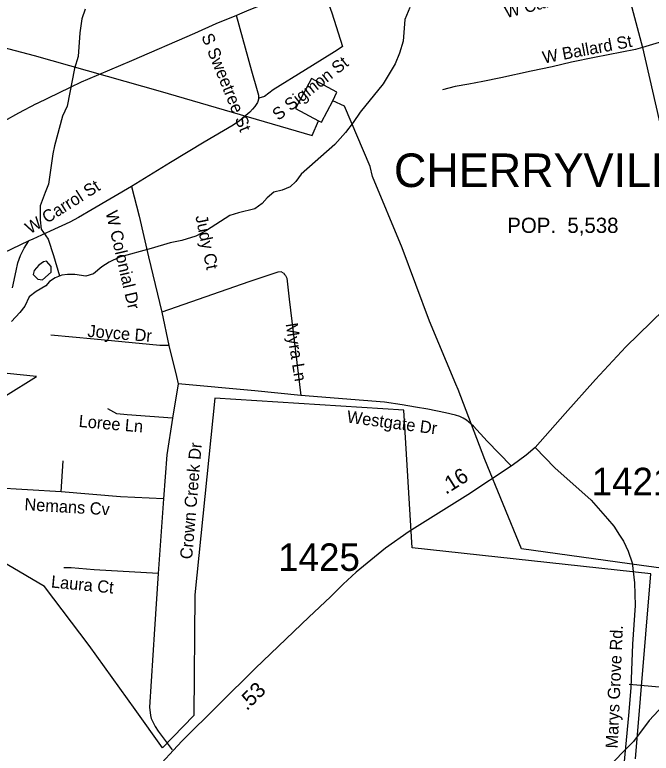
# Model space of a CAD drawing. Extents: x 1268485 to 1426702, y 514839 to 616766.
# Drawn here: x 1285826 to 1289245, y 595436 to 599406 of the extents above; entities that cross this region are included whole.
import ezdxf

# ---------------------------------------------------------------- set-up
doc = ezdxf.new("R2010")
doc.units = 0
for name, color, linetype in [('Old_Level_10', 7, 'Continuous'), ('Old_Level_11', 7, 'Continuous'), ('Old_Level_17', 7, 'Continuous'), ('Old_Level_32', 7, 'Continuous'), ('Old_Level_35', 7, 'Continuous'), ('Old_Level_48', 7, 'Continuous'), ('Old_Level_49', 7, 'Continuous'), ('Old_Level_56', 7, 'Continuous'), ('Old_Level_62', 7, 'Continuous'), ('Old_Level_8', 7, 'Continuous'), ('Old_Level_9', 7, 'Continuous')]:
    doc.layers.add(name, color=color, linetype=linetype)

msp = doc.modelspace()

# ---------------------------------------------------------------- linework, layer by layer
at = {"layer": 'Old_Level_32'}
for points in [[(1291373.236, 599052.963), (1291042.485, 598962.222), (1290896.068, 598918.096), (1290714.369, 598868.675), (1290626.166, 598839.552), (1290393.37, 598736.035), (1290251.442, 598663.453), (1290079.286, 598556.102), (1290045.769, 598531.391), (1289973.441, 598467.85), (1289871.596, 598364.18), (1289673.146, 598175.239), (1289517.331, 598019.095), (1289109.386, 597620.624), (1288945.325, 597445.883), (1288783.028, 597262.317), (1288622.05, 597079.622)], [(1288622.05, 597079.622), (1288572.393, 597038.158), (1288497.215, 596983.49), (1288260.148, 596824.586), (1287944.218, 596628.834), (1287817.925, 596537.729), (1287660.673, 596409.627), (1287589.144, 596345.233), (1287521.339, 596276.962), (1287404.685, 596167.653), (1287119.817, 595892.644), (1286723.931, 595500.009), (1286678.393, 595451.758), (1286614.957, 595384.542), (1286400.649, 595135.726), (1286252.429, 594959.218), (1286198.695, 594877.861), (1286130.586, 594756.275), (1286065.2, 594633.367), (1286021.61, 594555.394)], [(1288622.05, 597079.622), (1288726.94, 596969.93), (1288923.097, 596796.803), (1289010.597, 596695.735), (1289044.114, 596656.904), (1289074.104, 596609.248), (1289096.096, 596576.098), (1289121.978, 596523.235), (1289142.904, 596459.219), (1289154.67, 596351.428), (1289158.757, 596231.164), (1289145.135, 596022.353), (1289135.047, 595786.899), (1289122.674, 595639.228), (1289095.159, 595335.828), (1289082.775, 595157.988)]]:
    msp.add_lwpolyline(points, dxfattribs=at)
at = {"layer": 'Old_Level_35'}
for p, q in [((1289089.245, 599646.829), (1289197.512, 599230.009)), ((1289197.512, 599230.009), (1289304.755, 598761.055)), ((1286615.907, 597806.743), (1286654.149, 597627.681)), ((1286703.361, 597422.936), (1286672.603, 597238.236)), ((1286074.877, 596840.691), (1286085.949, 597008.988)), ((1286624.826, 596803.628), (1286595.606, 596402.392))]:
    msp.add_line(p, q, dxfattribs=at)
for points in [[(1287467.898, 599584.442), (1287422.274, 599565.167), (1287082.298, 599431.626), (1287032.88, 599410.353), (1287016.271, 599402.458)], [(1287467.898, 599584.442), (1287529.619, 599415.94), (1287587.238, 599235.699)], [(1287016.271, 599402.458), (1286905.338, 599357.705), (1286790.508, 599305.417), (1286451.967, 599159.574), (1286215.953, 599058.329), (1286182.119, 599043.463), (1286123.987, 599014.705), (1285942.516, 598927.916)], [(1287136.124, 598957.956), (1287136.636, 598971.746), (1287130.075, 598996.865), (1287099.727, 599103.236), (1287016.271, 599402.458)], [(1289594.083, 599362.114), (1289521.392, 599333.151), (1289376.42, 599284.707), (1289197.512, 599230.009)], [(1287587.238, 599235.699), (1287557.301, 599216.424), (1287529.721, 599198.79), (1287386.902, 599110.105), (1287214.351, 599003.324), (1287166.471, 598966.415), (1287136.124, 598957.956)], [(1289197.512, 599230.009), (1289161.218, 599220.269), (1288940.172, 599177.208), (1288817.038, 599151.269), (1288712.052, 599126.919), (1288600.298, 599102.98), (1288436.872, 599068.172), (1288339.985, 599047.513), (1288265.14, 599034.133), (1288192.45, 599020.394), (1288123.655, 599002.914)], [(1287136.124, 598957.956), (1287129.665, 598934.068), (1287115.106, 598912.435), (1287102.905, 598898.388), (1287089.372, 598883.164), (1287056.153, 598855.02), (1287032.367, 598835.899), (1286999.149, 598812.164), (1286844.027, 598721.685), (1286662.146, 598611.521), (1286452.583, 598483.876)], [(1285942.516, 598927.916), (1285941.388, 598927.353), (1285845.423, 598877.576), (1285769.349, 598833.541), (1285716.548, 598804.834), (1285656.263, 598774.179), (1285614.125, 598756.134), (1285562.657, 598736.602), (1285562.041, 598736.5)], [(1286452.583, 598483.876), (1286241.994, 598359.614), (1286167.355, 598316.195), (1286121.218, 598290.871), (1286015.001, 598242.94), (1285923.241, 598200.801), (1285901.095, 598190.856), (1285716.651, 598104.017)], [(1286452.583, 598483.876), (1286494.721, 598324.14), (1286544.856, 598104.889), (1286615.907, 597806.743)], [(1285814.255, 597938.899), (1285832.403, 598030.3), (1285842.758, 598071.926), (1285856.701, 598111.245), (1285875.771, 598151.076), (1285901.095, 598190.856)], [(1287270.125, 598017.075), (1287256.797, 598024.251), (1287239.265, 598021.996), (1287223.168, 598017.485), (1287083.528, 597970.99), (1286615.907, 597806.743)], [(1287270.125, 598017.075), (1287275.149, 598010.77), (1287280.48, 598003.951), (1287286.529, 597989.444), (1287299.96, 597877.229), (1287363.219, 597358.96)], [(1286654.149, 597627.681), (1286604.424, 597627.681), (1286252.042, 597662.437), (1286018.59, 597684.122)], [(1286654.149, 597627.681), (1286695.262, 597461.435), (1286703.361, 597422.936)], [(1287363.219, 597358.96), (1287115.516, 597384.541), (1286703.361, 597422.936)], [(1288492.646, 596981.101), (1288363.873, 597114.538), (1288289.952, 597194.15), (1288253.042, 597226.445), (1288235.1, 597238.236), (1288216.133, 597246.951), (1288193.987, 597253.102), (1288139.649, 597266.431), (1288044.299, 597285.449), (1287978.99, 597297.239), (1287906.094, 597310.055), (1287811.77, 597322.871), (1287699.402, 597332.611), (1287363.219, 597358.96)], [(1286672.603, 597238.236), (1286429.104, 597254.691), (1286373.535, 597260.997), (1286325.655, 597287.704)], [(1286672.603, 597238.236), (1286642.358, 597039.643), (1286624.826, 596803.628)], [(1286074.877, 596840.691), (1285711.524, 596863.298), (1285656.673, 596875.704)], [(1286624.826, 596803.628), (1286393.733, 596815.367), (1286074.877, 596840.691)], [(1286595.606, 596402.392), (1286251.837, 596422.692), (1286128.395, 596432.637), (1286088.615, 596433.509)], [(1286595.606, 596402.392), (1286575.614, 596103.683), (1286549.982, 595682.916), (1286554.083, 595638.317), (1286559.21, 595622.938), (1286579.715, 595579.826), (1286596.119, 595554.143), (1286671.578, 595454.641)], [(1289127.282, 595806.818), (1289369.346, 595786.518), (1289417.841, 595783.391), (1289457.108, 595781.649), (1289515.548, 595792.311), (1289613.05, 595811.894), (1289715.371, 595834.142), (1289774.631, 595843.933), (1289832.866, 595855.057), (1289888.128, 595866.643), (1289925.96, 595872.025), (1289962.049, 595873.307), (1289999.881, 595870.179), (1290033.202, 595862.644), (1290067.958, 595847.521), (1290100.972, 595826.145), (1290134.908, 595797.181), (1290170.484, 595754.427), (1290236.409, 595647.134), (1290262.963, 595601.766)]]:
    msp.add_lwpolyline(points, dxfattribs=at)
at = {"layer": 'Old_Level_48'}
for points in [[(1285440.364, 597149.866), (1285941.557, 597461.072), (1285239.886, 597532.39)], [(1289160.786, 595405.264), (1289243.583, 596401.2), (1287961.566, 596540.764), (1287915.791, 597281.367), (1286900.507, 597344.37), (1286793.585, 596287.566), (1286786.902, 595639.221), (1286619.838, 595464.167), (1286472.821, 595671.638), (1286225.566, 596015.261), (1285984.993, 596332.951), (1285189.767, 596799.759)]]:
    msp.add_lwpolyline(points, dxfattribs=at)
at = {"layer": 'Old_Level_49'}
for points in [[(1285440.364, 597149.866), (1285941.557, 597461.072), (1285239.886, 597532.39)], [(1289160.786, 595405.264), (1289243.583, 596401.2), (1287961.566, 596540.764), (1287915.791, 597281.367), (1286900.507, 597344.37), (1286793.585, 596287.566), (1286786.902, 595639.221), (1286619.838, 595464.167), (1286472.821, 595671.638), (1286225.566, 596015.261), (1285984.993, 596332.951), (1285189.767, 596799.759)]]:
    msp.add_lwpolyline(points, dxfattribs=at)
at = {"layer": 'Old_Level_56'}
for points in [[(1281527.068, 597048.671), (1281959.235, 597378.004), (1281983.877, 597409.325), (1282381.702, 597629.835), (1282734.399, 597815.234), (1282772.921, 597840.272), (1283101.299, 598010.353), (1283429.918, 598192.435), (1283882.463, 598447.462), (1284371.248, 598713.564), (1284930.959, 599014.058), (1285446.39, 599301.636), (1285512.31, 599296.107), (1285929.727, 599187.655), (1286607.573, 598994.921), (1287424.172, 598756.774), (1287458.18, 598835.93)], [(1287534.796, 598944.244), (1287555.919, 598989.642), (1287419.534, 599063.222), (1287333.672, 598903.069), (1287458.18, 598835.93)], [(1287458.18, 598835.93), (1287473.861, 598829.611), (1287534.796, 598944.244)], [(1290886.864, 595119.679), (1290648.677, 595523.675), (1290398.171, 595912.11), (1290183.061, 596279.623), (1290155.585, 596306.389), (1290106.148, 596325.593), (1289667.324, 596384.45), (1289617.364, 596387.657), (1289192.535, 596446.032), (1288548.235, 596535.837), (1288351.98, 597015.028), (1288207.068, 597390.733), (1288194.768, 597420.309), (1288053.998, 597758.798), (1287907.649, 598152.542), (1287746.901, 598536.77), (1287734.186, 598591.053), (1287598.028, 598914.556), (1287534.796, 598944.244)]]:
    msp.add_lwpolyline(points, dxfattribs=at)
at = {"layer": 'Old_Level_62'}
for points in [[(1286203.752, 599436.753), (1286186.528, 599385.131), (1286174.635, 599309.365), (1286165.51, 599181.565), (1286145.825, 599117.999), (1286106.967, 598914.793), (1286081.643, 598861.428), (1286039.71, 598702.359), (1286030.585, 598658.529), (1286006.594, 598495.051), (1285989.472, 598451.427), (1285962.748, 598379.843), (1285962.748, 598304.29), (1285966.944, 598253.922), (1286004.699, 598199.356), (1286034.063, 598111.212), (1286066.795, 598002.042)], [(1287949.053, 599445.98), (1287921.371, 599380.62), (1287912.553, 599264.766), (1287892.868, 599199.2), (1287869.493, 599141.785), (1287804.901, 599035.261), (1287681.05, 598882.189), (1287643.628, 598827.082), (1287602.412, 598774.076), (1287544.793, 598709.433), (1287364.654, 598549.749), (1287335.742, 598510.43), (1287304.984, 598481.21), (1287262.538, 598464.242), (1287218.247, 598453.323), (1287181.543, 598422.207), (1287154.681, 598390.885), (1287116.029, 598363.767), (1287027.344, 598341.929), (1286981.002, 598327.063), (1286854.997, 598246.067), (1286798.095, 598215.463), (1286723.661, 598193.266), (1286661.223, 598180.809), (1286558.389, 598149.282), (1286389.222, 598103.402), (1286332.525, 598076.796), (1286293.872, 598051.728), (1286248.863, 598012.769), (1286206.623, 598001.85), (1286148.798, 598009.283), (1286108.71, 598010.205), (1286078.67, 598006.976), (1286042.273, 597991.853), (1286011.721, 597972.578)], [(1285979.528, 598077.632), (1285954.359, 598060.843), (1285929.189, 598031.461), (1285924.994, 598010.474), (1285950.164, 597985.29), (1285975.334, 597981.093), (1286021.479, 598023.066), (1286021.479, 598052.448), (1285996.309, 598081.829), (1285979.528, 598077.632)], [(1286011.721, 597972.578), (1285993.266, 597948.997), (1285940.363, 597918.342), (1285903.658, 597889.225), (1285880.487, 597839.756), (1285853.625, 597806.384), (1285808.411, 597757.428)], [(1289541.077, 596393.165), (1289531.85, 596341.389), (1289529.697, 596255.37), (1289532.465, 596203.236), (1289519.342, 596157.56), (1289500.169, 596115.986), (1289474.948, 595980.549), (1289455.468, 595920.981), (1289432.194, 595869.462), (1289382.059, 595784.724), (1289332.334, 595717.877), (1289233.704, 595612.275), (1289148.915, 595498.267), (1288995.023, 595343.913)]]:
    msp.add_lwpolyline(points, dxfattribs=at)

# ---------------------------------------------------------------- texts
at = {"layer": 'Old_Level_10'}
for s, height, rotation, p in [('W Carroll St', 65.61666, 14.444147, (1288466.227, 599388.089)), ('S Sweetree St', 65.61666, 292.110961, (1286826.736, 599290.598)), ('W Ballard St', 65.61666, 10.718819, (1288667.522, 599143.979)), ('S Sigmon St', 65.61666, 38.229656, (1287241.762, 598834.671)), ('W Carrol St', 65.61666, 32.356506, (1285908.116, 598225.134)), ('W Colonial Dr', 65.61666, 283.144478, (1286313.092, 598344.727)), ('Judy Ct', 65.6167, 281.886228, (1286795.407, 598322.55)), ('Myra Ln', 65.6167, 279.111578, (1287280.379, 597744.307)), ('Joyce Dr', 65.6167, 355.380478, (1286214.419, 597675.027)), ('Westgate Dr', 65.61666, 352.391336, (1287606.87, 597214.315)), ('Loree Ln', 65.6167, 354.939575, (1286167.259, 597190.649)), ('Crown Creek Dr', 65.61666, 85.175872, (1286778.187, 596477.041)), ('Nemans Cv', 65.6167, 356.529808, (1285876.168, 596742.783)), ('Laura Ct', 65.6167, 354.385483, (1286018.55, 596327.37))]:
    msp.add_text(s, height=height, rotation=rotation, dxfattribs=at).set_placement(p)
at = {"layer": 'Old_Level_11'}
msp.add_text('Marys Grove Rd.', height=65.61666, rotation=87.546531, dxfattribs=at).set_placement((1289064.756, 595460.775))
at = {"layer": 'Old_Level_17'}
for s, rotation, p in [('.16', 32.226311, (1288141.644, 596824.952)), ('.53', 44.763831, (1287072.248, 595660.862))]:
    msp.add_text(s, height=82.0208, rotation=rotation, dxfattribs=at).set_placement(p)
at = {"layer": 'Old_Level_8'}
for s, p in [('1421', (1288924.924, 596823.233)), ('1425', (1287240.63, 596416.405))]:
    msp.add_text(s, height=147.6375, dxfattribs=at).set_placement(p)
at = {"layer": 'Old_Level_9'}
for s, height, p in [('CHERRYVILLE', 180.44583, (1287862.718, 598480.081)), ('POP.  5,538', 82.02083, (1288471.605, 598233.334))]:
    msp.add_text(s, height=height, dxfattribs=at).set_placement(p)

doc.saveas('drawing.dxf')
